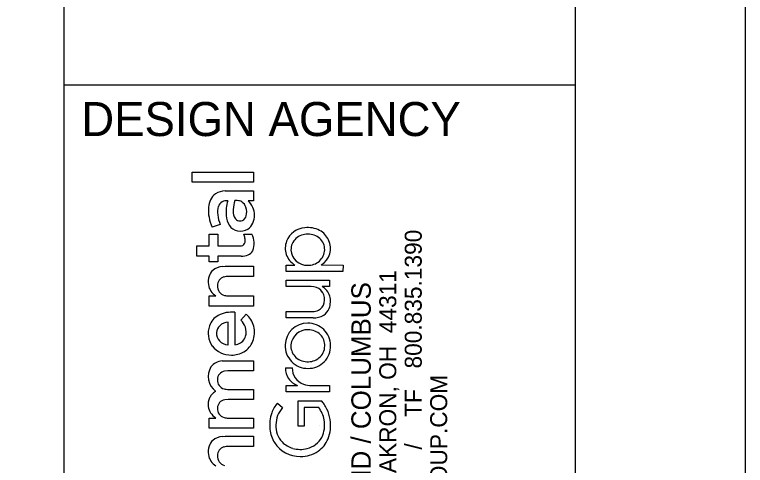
# Model space of a CAD drawing. Extents: x -0.3 to 34, y 0 to 22.
# Drawn here: x 31.854 to 34, y 3.382 to 4.707 of the extents above; entities that cross this region are included whole.
import ezdxf

# ---------------------------------------------------------------- set-up
doc = ezdxf.new("R2010")
doc.units = 0
for name, color, linetype in [('DR_P_Staging_Area', 7, 'Continuous'), ('MT_P_Drums', 7, 'Continuous'), ('SG_P_Poles', 7, 'Continuous')]:
    doc.layers.add(name, color=color, linetype=linetype)

msp = doc.modelspace()

# ---------------------------------------------------------------- linework, layer by layer
at = {"layer": 'DR_P_Staging_Area'}
msp.add_lwpolyline([(0, 0), (34, 0), (34, 22), (0, 22)], close=True, dxfattribs=at)
at = {"layer": 'MT_P_Drums'}
for p, q in [((32, 0.5), (32, 21.5)), ((32, 4.5), (33.5, 4.5))]:
    msp.add_line(p, q, dxfattribs=at)
msp.add_lwpolyline([(1.5, 21.5), (33.5, 21.5), (33.5, 0.5), (1.5, 0.5)], close=True, dxfattribs=at)
at = {"layer": 'SG_P_Poles'}
for p, q in [((32.3756, 4.2141), (32.3756, 4.244)), ((32.3756, 4.244), (32.5557, 4.244)), ((32.5557, 4.244), (32.5557, 4.2141)), ((32.5557, 4.2141), (32.3756, 4.2141)), ((32.4727, 4.189), (32.5555, 4.1892)), ((32.5555, 4.1892), (32.5557, 4.1596)), ((32.5557, 4.1596), (32.5397, 4.1596)), ((32.4582, 4.0904), (32.4343, 4.0823)), ((32.4254, 4.027), (32.4255, 4.0621)), ((32.4255, 4.0621), (32.4511, 4.0621)), ((32.4511, 4.0621), (32.4512, 4.027)), ((32.527, 4.0616), (32.5511, 4.0616)), ((32.3896, 3.9972), (32.3896, 4.027)), ((32.3896, 4.027), (32.4254, 4.027)), ((32.4512, 4.027), (32.515, 4.027)), ((32.515, 4.027), (32.52, 4.0275)), ((32.4254, 3.9972), (32.3896, 3.9972)), ((32.4254, 3.9807), (32.4254, 3.9972)), ((32.5197, 3.9972), (32.4511, 3.9972)), ((32.4511, 3.9972), (32.4511, 3.9807)), ((32.4511, 3.9807), (32.4254, 3.9807)), ((32.6515, 3.9521), (32.6515, 3.9711)), ((32.6515, 3.9711), (32.6771, 3.9711)), ((32.7549, 3.9713), (32.8186, 3.9711)), ((32.8186, 3.9711), (32.8184, 3.9521)), ((32.4644, 3.9669), (32.4729, 3.9673)), ((32.4729, 3.9673), (32.5557, 3.9673)), ((32.5557, 3.9673), (32.5557, 3.9375)), ((32.8184, 3.9521), (32.6515, 3.9521)), ((32.5557, 3.9375), (32.4814, 3.9375)), ((32.6515, 3.908), (32.6515, 3.9267)), ((32.6515, 3.9267), (32.7791, 3.9266)), ((32.7791, 3.9266), (32.7791, 3.908)), ((32.7249, 3.908), (32.6515, 3.908)), ((32.7328, 3.9073), (32.7249, 3.908)), ((32.7791, 3.908), (32.7569, 3.908)), ((32.4254, 3.8503), (32.4254, 3.8802)), ((32.4254, 3.8802), (32.4455, 3.8802)), ((32.4822, 3.8802), (32.5557, 3.8802)), ((32.5557, 3.8802), (32.5557, 3.8504)), ((32.5557, 3.8504), (32.4254, 3.8503)), ((32.5011, 3.8321), (32.5012, 3.7366)), ((32.5188, 3.8093), (32.5342, 3.8266)), ((32.6515, 3.8344), (32.7291, 3.8345)), ((32.6517, 3.8154), (32.6515, 3.8344)), ((32.4814, 3.7364), (32.4814, 3.803)), ((32.7307, 3.8154), (32.6517, 3.8154)), ((32.4802, 3.7363), (32.4814, 3.7364)), ((32.4633, 3.6891), (32.4726, 3.6897)), ((32.4726, 3.6897), (32.5556, 3.6897)), ((32.5556, 3.6897), (32.5557, 3.6598)), ((32.6493, 3.6691), (32.6698, 3.6691)), ((32.4806, 3.6598), (32.471, 3.6588)), ((32.5557, 3.6598), (32.4806, 3.6598)), ((32.4822, 3.6055), (32.5557, 3.6055)), ((32.5557, 3.6055), (32.5557, 3.5757)), ((32.6515, 3.598), (32.6515, 3.617)), ((32.6515, 3.617), (32.6848, 3.617)), ((32.726, 3.617), (32.7791, 3.617)), ((32.7791, 3.617), (32.779, 3.598)), ((32.4444, 3.5992), (32.4446, 3.6007)), ((32.779, 3.598), (32.6515, 3.598)), ((32.4809, 3.5757), (32.4714, 3.5747)), ((32.5557, 3.5757), (32.4809, 3.5757)), ((32.6264, 3.5655), (32.6411, 3.5524)), ((32.6868, 3.5718), (32.7552, 3.5719)), ((32.6868, 3.4978), (32.6868, 3.5718)), ((32.7045, 3.5524), (32.7043, 3.4978)), ((32.7474, 3.5523), (32.7045, 3.5524)), ((32.4254, 3.4915), (32.4254, 3.5214)), ((32.4254, 3.5214), (32.4451, 3.5214)), ((32.4821, 3.5214), (32.5557, 3.5214)), ((32.5557, 3.5214), (32.5557, 3.4916)), ((32.7043, 3.4978), (32.6868, 3.4978)), ((32.75, 3.5), (32.75, 3.5)), ((32.5557, 3.4916), (32.4254, 3.4915)), ((32.4644, 3.4674), (32.4729, 3.4678)), ((32.4729, 3.4678), (32.5557, 3.4678)), ((32.5557, 3.4678), (32.5557, 3.438)), ((32.5557, 3.438), (32.4814, 3.438))]:
    msp.add_line(p, q, dxfattribs=at)
msp.add_lwpolyline([(32.3756, 4.2141), (32.3756, 4.244), (32.5557, 4.244), (32.5557, 4.2141)], close=True, dxfattribs=at)
for points in [[(32.4727, 4.189), (32.5555, 4.1892), (32.5557, 4.1596)], [(32.5557, 4.1596), (32.5397, 4.1596)], [(32.4582, 4.0904), (32.4343, 4.0823)], [(32.5197, 3.9972), (32.4511, 3.9972), (32.4511, 3.9807), (32.4254, 3.9807), (32.4254, 3.9972), (32.3896, 3.9972), (32.3896, 4.027), (32.4254, 4.027), (32.4255, 4.0621), (32.4511, 4.0621), (32.4512, 4.027), (32.515, 4.027), (32.52, 4.0275)], [(32.527, 4.0616), (32.5511, 4.0616)], [(32.7549, 3.9713), (32.8186, 3.9711), (32.8184, 3.9521), (32.6515, 3.9521)], [(32.6515, 3.9521), (32.6515, 3.9711), (32.6771, 3.9711)], [(32.4644, 3.9669), (32.4729, 3.9673), (32.5557, 3.9673), (32.5557, 3.9375), (32.4814, 3.9375)], [(32.7328, 3.9073), (32.7249, 3.908), (32.6515, 3.908), (32.6515, 3.9267), (32.7791, 3.9266), (32.7791, 3.908), (32.7569, 3.908)], [(32.4254, 3.8503), (32.4254, 3.8802), (32.4455, 3.8802)], [(32.4822, 3.8802), (32.5557, 3.8802), (32.5557, 3.8504), (32.4254, 3.8503)], [(32.5011, 3.8321), (32.5012, 3.7366)], [(32.5188, 3.8093), (32.5342, 3.8266)], [(32.7307, 3.8154), (32.6517, 3.8154), (32.6515, 3.8344), (32.7291, 3.8345)], [(32.4802, 3.7363), (32.4814, 3.7364), (32.4814, 3.803)], [(32.4633, 3.6891), (32.4726, 3.6897), (32.5556, 3.6897), (32.5557, 3.6598), (32.4806, 3.6598), (32.471, 3.6588)], [(32.6493, 3.6691), (32.6698, 3.6691)], [(32.4822, 3.6055), (32.5557, 3.6055), (32.5557, 3.5757), (32.4809, 3.5757), (32.4714, 3.5747)], [(32.6515, 3.598), (32.6515, 3.617), (32.6848, 3.617)], [(32.726, 3.617), (32.7791, 3.617), (32.779, 3.598), (32.6515, 3.598)], [(32.4444, 3.5992), (32.4446, 3.6007)], [(32.6264, 3.5655), (32.6411, 3.5524)], [(32.7474, 3.5523), (32.7045, 3.5524), (32.7043, 3.4978), (32.6868, 3.4978), (32.6868, 3.5718), (32.7552, 3.5719)], [(32.4254, 3.4915), (32.4254, 3.5214), (32.4451, 3.5214)], [(32.4821, 3.5214), (32.5557, 3.5214), (32.5557, 3.4916), (32.4254, 3.4915)], [(32.4644, 3.4674), (32.4729, 3.4678), (32.5557, 3.4678), (32.5557, 3.438), (32.4814, 3.438)]]:
    msp.add_lwpolyline(points, dxfattribs=at)
for centre, radius, start, end in [((32.4745, 4.1326), 0.0565, 91.8942, 122.6317), ((32.4745, 4.1326), 0.0565, 91.8942, 122.6317), ((32.4685, 4.1447), 0.043, 124.537, 155.6594), ((32.4685, 4.1447), 0.043, 124.537, 155.6594), ((32.5364, 4.1308), 0.113, 174.6101, 205.3899), ((32.5364, 4.1308), 0.113, 174.6101, 205.3899), ((32.4882, 4.1361), 0.0646, 155.9764, 175.3149), ((32.4882, 4.1361), 0.0646, 155.9764, 175.3149), ((32.5076, 4.1265), 0.0576, 163.1369, 188.1675), ((32.5076, 4.1265), 0.0576, 163.1369, 188.1675), ((32.4753, 4.1356), 0.024, 119.4252, 161.6629), ((32.4753, 4.1356), 0.024, 119.4252, 161.6629), ((32.4779, 4.1278), 0.0321, 85.3802, 116.6222), ((32.4779, 4.1278), 0.0321, 85.3802, 116.6222), ((32.5879, 4.1251), 0.1129, 162.0821, 184.5285), ((32.5879, 4.1251), 0.1129, 162.0821, 184.5285), ((32.5801, 4.1313), 0.0841, 159.8366, 178.0362), ((32.5801, 4.1313), 0.0841, 159.8366, 178.0362), ((32.5051, 4.1074), 0.053, 79.6696, 94.2322), ((32.5051, 4.1074), 0.053, 79.6696, 94.2322), ((32.5089, 4.1364), 0.0238, 56.8913, 76.2149), ((32.5089, 4.1364), 0.0238, 56.8913, 76.2149), ((32.5052, 4.1318), 0.0297, 17.5984, 55.7282), ((32.5052, 4.1318), 0.0297, 17.5984, 55.7282), ((32.5055, 4.1191), 0.0529, 358.0746, 49.762), ((32.5055, 4.1191), 0.0529, 358.0746, 49.762), ((32.5466, 4.1303), 0.0506, 175.5903, 199.8857), ((32.5466, 4.1303), 0.0506, 175.5903, 199.8857), ((32.4916, 4.1264), 0.0443, 345.9408, 18.9919), ((32.4916, 4.1264), 0.0443, 345.9408, 18.9919), ((32.5473, 4.1297), 0.0973, 186.7598, 203.7981), ((32.5473, 4.1297), 0.0973, 186.7598, 203.7981), ((32.5328, 4.1187), 0.0575, 182.5676, 213.7144), ((32.5328, 4.1187), 0.0575, 182.5676, 213.7144), ((32.5164, 4.1189), 0.0184, 198.2844, 293.3081), ((32.5164, 4.1189), 0.0184, 198.2844, 293.3081), ((32.5152, 4.1199), 0.0199, 295.2883, 347.4639), ((32.5152, 4.1199), 0.0199, 295.2883, 347.4639), ((32.5019, 4.1168), 0.0566, 336.016, 0.5951), ((32.5019, 4.1168), 0.0566, 336.016, 0.5951), ((32.5149, 4.1078), 0.0366, 215.0668, 259.8133), ((32.5149, 4.1078), 0.0366, 215.0668, 259.8133), ((32.5175, 4.1131), 0.0423, 257.5256, 300.882), ((32.5175, 4.1131), 0.0423, 257.5256, 300.882), ((32.5175, 4.1097), 0.0394, 303.4436, 336.18), ((32.5175, 4.1097), 0.0394, 303.4436, 336.18), ((32.7108, 4.0182), 0.0624, 93.9866, 158.3119), ((32.7108, 4.0182), 0.0624, 93.9866, 158.3119), ((32.7156, 4.0065), 0.0746, 62.6889, 97.0135), ((32.7156, 4.0065), 0.0746, 62.6889, 97.0135), ((32.4863, 4.042), 0.0452, 10.1545, 25.723), ((32.4863, 4.042), 0.0452, 10.1545, 25.723), ((32.503, 4.0351), 0.0549, 336.589, 28.8991), ((32.503, 4.0351), 0.0549, 336.589, 28.8991), ((32.7138, 4.0102), 0.0513, 87.8965, 131.1812), ((32.7138, 4.0102), 0.0513, 87.8965, 131.1812), ((32.7175, 4.0102), 0.0513, 49.9089, 92.0363), ((32.7175, 4.0102), 0.0513, 49.9089, 92.0363), ((32.7212, 4.0191), 0.0608, 25.0657, 61.9602), ((32.7212, 4.0191), 0.0608, 25.0657, 61.9602), ((32.5184, 4.04), 0.0126, 277.6142, 353.7918), ((32.5184, 4.04), 0.0126, 277.6142, 353.7918), ((32.4957, 4.0436), 0.0356, 351.914, 10.2059), ((32.4957, 4.0436), 0.0356, 351.914, 10.2059), ((32.707, 4.0202), 0.0581, 158.656, 198.171), ((32.707, 4.0202), 0.0581, 158.656, 198.171), ((32.7092, 4.0167), 0.0434, 132.3289, 182.0949), ((32.7092, 4.0167), 0.0434, 132.3289, 182.0949), ((32.7215, 4.0173), 0.0433, 358.0487, 47.9447), ((32.7215, 4.0173), 0.0433, 358.0487, 47.9447), ((32.7245, 4.02), 0.0574, 301.9776, 25.6418), ((32.7245, 4.02), 0.0574, 301.9776, 25.6418), ((32.5291, 4.0261), 0.0275, 292.6889, 332.0598), ((32.5291, 4.0261), 0.0275, 292.6889, 332.0598), ((32.7135, 4.0181), 0.0478, 183.5974, 271.7045), ((32.7135, 4.0181), 0.0478, 183.5974, 271.7045), ((32.7172, 4.018), 0.0477, 267.3149, 357.4019), ((32.7172, 4.018), 0.0477, 267.3149, 357.4019), ((32.5209, 4.0486), 0.0514, 268.6727, 291.5235), ((32.5209, 4.0486), 0.0514, 268.6727, 291.5235), ((32.7103, 4.0243), 0.0627, 200.8399, 238.0162), ((32.7103, 4.0243), 0.0627, 200.8399, 238.0162), ((32.4635, 3.9255), 0.0402, 132.2238, 161.6823), ((32.4635, 3.9255), 0.0402, 132.2238, 161.6823), ((32.4687, 3.9172), 0.0499, 94.9706, 130.2248), ((32.4687, 3.9172), 0.0499, 94.9706, 130.2248), ((32.4787, 3.9211), 0.056, 162.274, 187.7917), ((32.4787, 3.9211), 0.056, 162.274, 187.7917), ((32.4748, 3.9116), 0.025, 103.6868, 182.214), ((32.4748, 3.9116), 0.025, 103.6868, 182.214), ((32.4811, 3.8915), 0.046, 89.6051, 105.3303), ((32.4811, 3.8915), 0.046, 89.6051, 105.3303), ((32.4703, 3.9209), 0.0476, 188.9646, 238.6987), ((32.4703, 3.9209), 0.0476, 188.9646, 238.6987), ((32.4774, 3.9085), 0.0276, 175.5844, 255.1382), ((32.4774, 3.9085), 0.0276, 175.5844, 255.1382), ((32.7271, 3.87), 0.0377, 33.5008, 81.3295), ((32.7271, 3.87), 0.0377, 33.5008, 81.3295), ((32.7324, 3.8648), 0.0496, 17.6221, 60.3897), ((32.7324, 3.8648), 0.0496, 17.6221, 60.3897), ((32.7241, 3.8695), 0.0405, 346.5618, 31.7539), ((32.7241, 3.8695), 0.0405, 346.5618, 31.7539), ((32.4818, 3.9224), 0.0421, 254.0891, 270.5284), ((32.4818, 3.9224), 0.0421, 254.0891, 270.5284), ((32.7234, 3.8641), 0.0584, 339.162, 15.6148), ((32.7234, 3.8641), 0.0584, 339.162, 15.6148), ((32.7337, 3.8662), 0.0304, 294.6321, 348.4863), ((32.7337, 3.8662), 0.0304, 294.6321, 348.4863), ((32.739, 3.859), 0.042, 303.1039, 338.1561), ((32.739, 3.859), 0.042, 303.1039, 338.1561), ((32.4789, 3.7737), 0.0558, 118.8294, 160.6224), ((32.4789, 3.7737), 0.0558, 118.8294, 160.6224), ((32.4918, 3.7487), 0.0839, 83.6212, 118.2845), ((32.4918, 3.7487), 0.0839, 83.6212, 118.2845), ((32.494, 3.7763), 0.0644, 13.5328, 51.3627), ((32.494, 3.7763), 0.0644, 13.5328, 51.3627), ((32.7275, 3.8808), 0.0463, 271.952, 294.0894), ((32.7275, 3.8808), 0.0463, 271.952, 294.0894), ((32.7321, 3.8726), 0.0571, 268.627, 301.4778), ((32.7321, 3.8726), 0.0571, 268.627, 301.4778), ((32.4844, 3.7607), 0.0424, 94.0131, 130.8806), ((32.4844, 3.7607), 0.0424, 94.0131, 130.8806), ((32.4803, 3.7702), 0.0549, 19.0387, 45.4432), ((32.4803, 3.7702), 0.0549, 19.0387, 45.4432), ((32.7143, 3.7348), 0.0655, 89.4821, 178.7775), ((32.7143, 3.7348), 0.0655, 89.4821, 178.7775), ((32.7158, 3.7341), 0.0662, 0.4227, 90.7613), ((32.7158, 3.7341), 0.0662, 0.4227, 90.7613), ((32.487, 3.7707), 0.0644, 160.5214, 215.7815), ((32.487, 3.7707), 0.0644, 160.5214, 215.7815), ((32.477, 3.7709), 0.0298, 132.9855, 177.1802), ((32.477, 3.7709), 0.0298, 132.9855, 177.1802), ((32.4872, 3.7743), 0.047, 344.6072, 17.0067), ((32.4872, 3.7743), 0.047, 344.6072, 17.0067), ((32.4829, 3.7738), 0.0758, 339.3543, 13.3771), ((32.4829, 3.7738), 0.0758, 339.3543, 13.3771), ((32.714, 3.7324), 0.0485, 87.6883, 175.017), ((32.714, 3.7324), 0.0485, 87.6883, 175.017), ((32.7166, 3.7304), 0.0505, 44.912, 90.7591), ((32.7166, 3.7304), 0.0505, 44.912, 90.7591), ((32.4782, 3.7697), 0.0311, 175.0014, 223.2876), ((32.4782, 3.7697), 0.0311, 175.0014, 223.2876), ((32.499, 3.7718), 0.035, 288.0108, 343.5536), ((32.499, 3.7718), 0.035, 288.0108, 343.5536), ((32.7196, 3.7345), 0.0455, 358.3228, 43.8349), ((32.7196, 3.7345), 0.0455, 358.3228, 43.8349), ((32.4855, 3.7783), 0.0423, 225.0645, 262.797), ((32.4855, 3.7783), 0.0423, 225.0645, 262.797), ((32.5013, 3.7568), 0.0202, 269.7004, 294.8729), ((32.5013, 3.7568), 0.0202, 269.7004, 294.8729), ((32.4955, 3.7698), 0.0626, 300.9439, 338.7322), ((32.4955, 3.7698), 0.0626, 300.9439, 338.7322), ((32.7148, 3.7334), 0.0661, 177.5373, 270.9452), ((32.7148, 3.7334), 0.0661, 177.5373, 270.9452), ((32.7108, 3.7331), 0.0453, 175.5147, 221.4205), ((32.7108, 3.7331), 0.0453, 175.5147, 221.4205), ((32.7167, 3.7327), 0.0654, 269.3083, 1.6791), ((32.7167, 3.7327), 0.0654, 269.3083, 1.6791), ((32.4891, 3.7752), 0.0687, 217.7434, 271.6561), ((32.4891, 3.7752), 0.0687, 217.7434, 271.6561), ((32.492, 3.777), 0.0706, 269.2053, 300.3357), ((32.492, 3.777), 0.0706, 269.2053, 300.3357), ((32.7193, 3.7337), 0.0457, 308.9038, 359.3095), ((32.7193, 3.7337), 0.0457, 308.9038, 359.3095), ((32.714, 3.7373), 0.0505, 222.6626, 268.3733), ((32.714, 3.7373), 0.0505, 222.6626, 268.3733), ((32.7157, 3.7386), 0.0518, 266.5531, 308.6725), ((32.7157, 3.7386), 0.0518, 266.5531, 308.6725), ((32.4759, 3.6437), 0.0532, 148.2879, 233.9556), ((32.4759, 3.6437), 0.0532, 148.2879, 233.9556), ((32.4664, 3.644), 0.0452, 93.9112, 142.3072), ((32.4664, 3.644), 0.0452, 93.9112, 142.3072), ((32.6988, 3.6666), 0.0495, 177.1621, 216.2802), ((32.6988, 3.6666), 0.0495, 177.1621, 216.2802), ((32.7173, 3.6664), 0.0476, 176.7699, 252.1504), ((32.7173, 3.6664), 0.0476, 176.7699, 252.1504), ((32.4738, 3.635), 0.024, 96.7576, 181.6251), ((32.4738, 3.635), 0.024, 96.7576, 181.6251), ((32.4758, 3.6324), 0.026, 175.8157, 256.1672), ((32.4758, 3.6324), 0.026, 175.8157, 256.1672), ((32.7098, 3.6755), 0.0637, 216.9153, 246.8862), ((32.7098, 3.6755), 0.0637, 216.9153, 246.8862), ((32.4817, 3.6505), 0.045, 254.3463, 270.6103), ((32.4817, 3.6505), 0.045, 254.3463, 270.6103), ((32.7269, 3.6917), 0.0747, 251.1388, 269.3469), ((32.7269, 3.6917), 0.0747, 251.1388, 269.3469), ((32.4619, 3.5645), 0.0387, 139.5245, 154.847), ((32.4619, 3.5645), 0.0387, 139.5245, 154.847), ((32.4638, 3.5627), 0.0414, 117.9163, 139.243), ((32.4638, 3.5627), 0.0414, 117.9163, 139.243), ((32.4714, 3.5612), 0.0488, 156.0638, 187.3493), ((32.4714, 3.5612), 0.0488, 156.0638, 187.3493), ((32.4742, 3.5506), 0.0243, 96.5532, 179.949), ((32.4742, 3.5506), 0.0243, 96.5532, 179.949), ((32.7016, 3.5019), 0.0986, 139.7948, 159.137), ((32.7016, 3.5019), 0.0986, 139.7948, 159.137), ((32.725, 3.5394), 0.0444, 30.9891, 47.161), ((32.725, 3.5394), 0.0444, 30.9891, 47.161), ((32.6709, 3.5002), 0.1111, 25.3031, 33.9618), ((32.6709, 3.5002), 0.1111, 25.3031, 33.9618), ((32.4646, 3.5597), 0.0418, 186.5579, 213.3885), ((32.4646, 3.5597), 0.0418, 186.5579, 213.3885), ((32.4761, 3.5486), 0.0263, 175.722, 255.7863), ((32.4761, 3.5486), 0.0263, 175.722, 255.7863), ((32.699, 3.5008), 0.0775, 138.258, 179.7006), ((32.699, 3.5008), 0.0775, 138.258, 179.7006), ((32.6789, 3.501), 0.0856, 10.0751, 36.8319), ((32.6789, 3.501), 0.0856, 10.0751, 36.8319), ((32.6704, 3.4999), 0.1117, 8.8034, 25.3348), ((32.6704, 3.4999), 0.1117, 8.8034, 25.3348), ((32.4789, 3.5708), 0.0598, 214.7043, 235.6872), ((32.4789, 3.5708), 0.0598, 214.7043, 235.6872), ((32.4819, 3.5652), 0.0438, 253.6672, 270.1498), ((32.4819, 3.5652), 0.0438, 253.6672, 270.1498), ((32.7187, 3.4997), 0.1154, 161.1438, 185.6281), ((32.7187, 3.4997), 0.1154, 161.1438, 185.6281), ((32.6881, 3.4973), 0.0668, 176.6658, 223.6912), ((32.6881, 3.4973), 0.0668, 176.6658, 223.6912), ((32.6842, 3.5006), 0.0804, 333.4669, 11.0367), ((32.6842, 3.5006), 0.0804, 333.4669, 11.0367), ((32.6756, 3.4998), 0.1065, 338.2887, 9.2855), ((32.6756, 3.4998), 0.1065, 338.2887, 9.2855), ((32.6934, 3.497), 0.0899, 185.5077, 212.0129), ((32.6934, 3.497), 0.0899, 185.5077, 212.0129), ((32.4635, 3.426), 0.0402, 132.2238, 161.6823), ((32.4635, 3.426), 0.0402, 132.2238, 161.6823), ((32.4687, 3.4177), 0.0499, 94.9706, 130.2248), ((32.4687, 3.4177), 0.0499, 94.9706, 130.2248), ((32.6987, 3.4955), 0.0652, 282.8815, 331.8147), ((32.6987, 3.4955), 0.0652, 282.8815, 331.8147), ((32.6984, 3.4917), 0.0824, 305.0306, 337.6757), ((32.6984, 3.4917), 0.0824, 305.0306, 337.6757), ((32.4787, 3.4216), 0.056, 162.274, 187.7917), ((32.4787, 3.4216), 0.056, 162.274, 187.7917), ((32.4748, 3.4121), 0.025, 103.6868, 182.214), ((32.4748, 3.4121), 0.025, 103.6868, 182.214), ((32.4811, 3.392), 0.046, 89.6051, 105.3303), ((32.4811, 3.392), 0.046, 89.6051, 105.3303), ((32.6921, 3.4975), 0.0891, 212.7022, 270.714), ((32.6921, 3.4975), 0.0891, 212.7022, 270.714), ((32.6905, 3.5001), 0.0704, 224.0215, 253.88), ((32.6905, 3.5001), 0.0704, 224.0215, 253.88), ((32.4703, 3.4214), 0.0476, 188.9646, 238.6987), ((32.4703, 3.4214), 0.0476, 188.9646, 238.6987), ((32.6932, 3.5125), 0.0831, 254.4535, 283.9512), ((32.6932, 3.5125), 0.0831, 254.4535, 283.9512), ((32.6943, 3.4998), 0.0914, 269.3273, 304.1963), ((32.6943, 3.4998), 0.0914, 269.3273, 304.1963), ((32.4774, 3.409), 0.0276, 175.5844, 255.1382), ((32.4774, 3.409), 0.0276, 175.5844, 255.1382)]:
    msp.add_arc(centre, radius, start, end, dxfattribs=at)

# ---------------------------------------------------------------- texts
msp.add_text('DESIGN AGENCY', height=0.1, dxfattribs=at).set_placement((32.05, 4.35))
for s, height, p in [('800.835.1390', 0.049846, (33.0497, 3.6671)), ('450 GRANT ST., AKRON, OH  44311', 0.049846, (32.9749, 2.8374)), ('AKRON / CLEVELAND / COLUMBUS', 0.056969, (32.9001, 2.638)), ('ENVDESIGNGROUP.COM', 0.049846, (33.1244, 2.8374)), ('TF', 0.04985, (33.0497, 3.5246)), ('/  ', 0.04985, (33.0497, 3.4288))]:
    msp.add_text(s, height=height, rotation=90, dxfattribs=at).set_placement(p)

doc.saveas('drawing.dxf')
